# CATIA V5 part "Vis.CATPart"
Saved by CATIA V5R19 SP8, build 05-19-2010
Part number: Vis
Publications: "Diametre vis", "diametre_gorge_vis", "diametre_tete_vis"
Bounding box of the stored display mesh (mm): x -30 to 30, y -3 to 3, z -88.353 to -5.5
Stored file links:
  G:\EU_thinkMotion\CFAO_2010\MMS_groupe3\MMS_groupe3\A reprendre\ftixier\florent-tixier\florent-tixier\Vis.CATPart
  C:\Users\Azote\Desktop\CFAO\coupe_tube.CATProduct
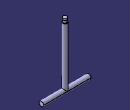
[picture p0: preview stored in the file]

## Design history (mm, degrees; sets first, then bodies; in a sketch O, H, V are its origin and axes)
Parameters
  `Diametre vis` = 6 mm
  diametre_gorge_vis = 4 mm
  diametre_tete_vis = 5 mm
External parameters (linked from other documents)
  External.prodondeur_trou = 10 mm
  External.profondeur_lamage = 2 mm
Set1
  Line1 "suport_axe_rouleau": linked copy from another document
  Line2 "Axe_vis": linked copy from another document
Body1 (main body)
  Sketch1 on yz-plane, origin (0, 0, 0), H (0, 1, 0), V (0, 0, 1)
    point P1 (0, -5.5)
    line L1 (0, -5.5) -> (2.5, -5.5)
    line L2 (2.5, -5.5) -> (2.5, -7.5)
    line L3 (2.5, -7.5) -> (2, -7.5)
    line L4 (2, -7.5) -> (2, -11)
    line L5 (2, -11) -> (3, -11)
    line L6 (3, -11) -> (3, -85.5)
    line L7 (3, -85.5) -> (0, -85.5)
    point P8 (0, -85.5)
    line L8 (0, -85.5) -> (0, -5.5)
    reference projected line E1 (20, 0) -> (-20, 0) from Line1
    distance L8 L4 = 2 {= diametre_gorge_vis /2}
    length L1 = 2.5 {= diametre_tete_vis /2}
    distance L6 L8 = 3 {= `Diametre vis` /2}
    length L4 = 3.5
    length L2 = 2 {= External.profondeur_lamage}
    distance L1 E1 = 5.5
    length L8 = 80
    coincidence: P1 V, P8 V
    horizontal: L1 H, L3 H, L5 H, L7 H
    vertical: L2 V, L4 V, L6 V, L8 V
  Shaft1: profile Sketch1, axis Line2, angle 360
  Sketch2 on yz-plane, origin (0, 0, 0), H (0, 1, 0), V (0, 0, 1)
    circle A1 centre (0, -85.5) radius 3
    point P1 (0, -85.5)
    reference projected line E1 (-3, -85.5) -> (3, -85.5) from edge [face of Shaft1 from Sketch1.L7 | face of Shaft1 from Sketch1.L6]
    radius A1 = 3 {= `Diametre vis` /2}
    distance A1 E1 = 3 {= `Diametre vis` /2}
    coincidence: P1 V
  Pad1: profile Sketch2, direction (1, 0, 0), length 30, mirrored extent
Relations
  Sketch1.length(L4) = 4mm (deactivated)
